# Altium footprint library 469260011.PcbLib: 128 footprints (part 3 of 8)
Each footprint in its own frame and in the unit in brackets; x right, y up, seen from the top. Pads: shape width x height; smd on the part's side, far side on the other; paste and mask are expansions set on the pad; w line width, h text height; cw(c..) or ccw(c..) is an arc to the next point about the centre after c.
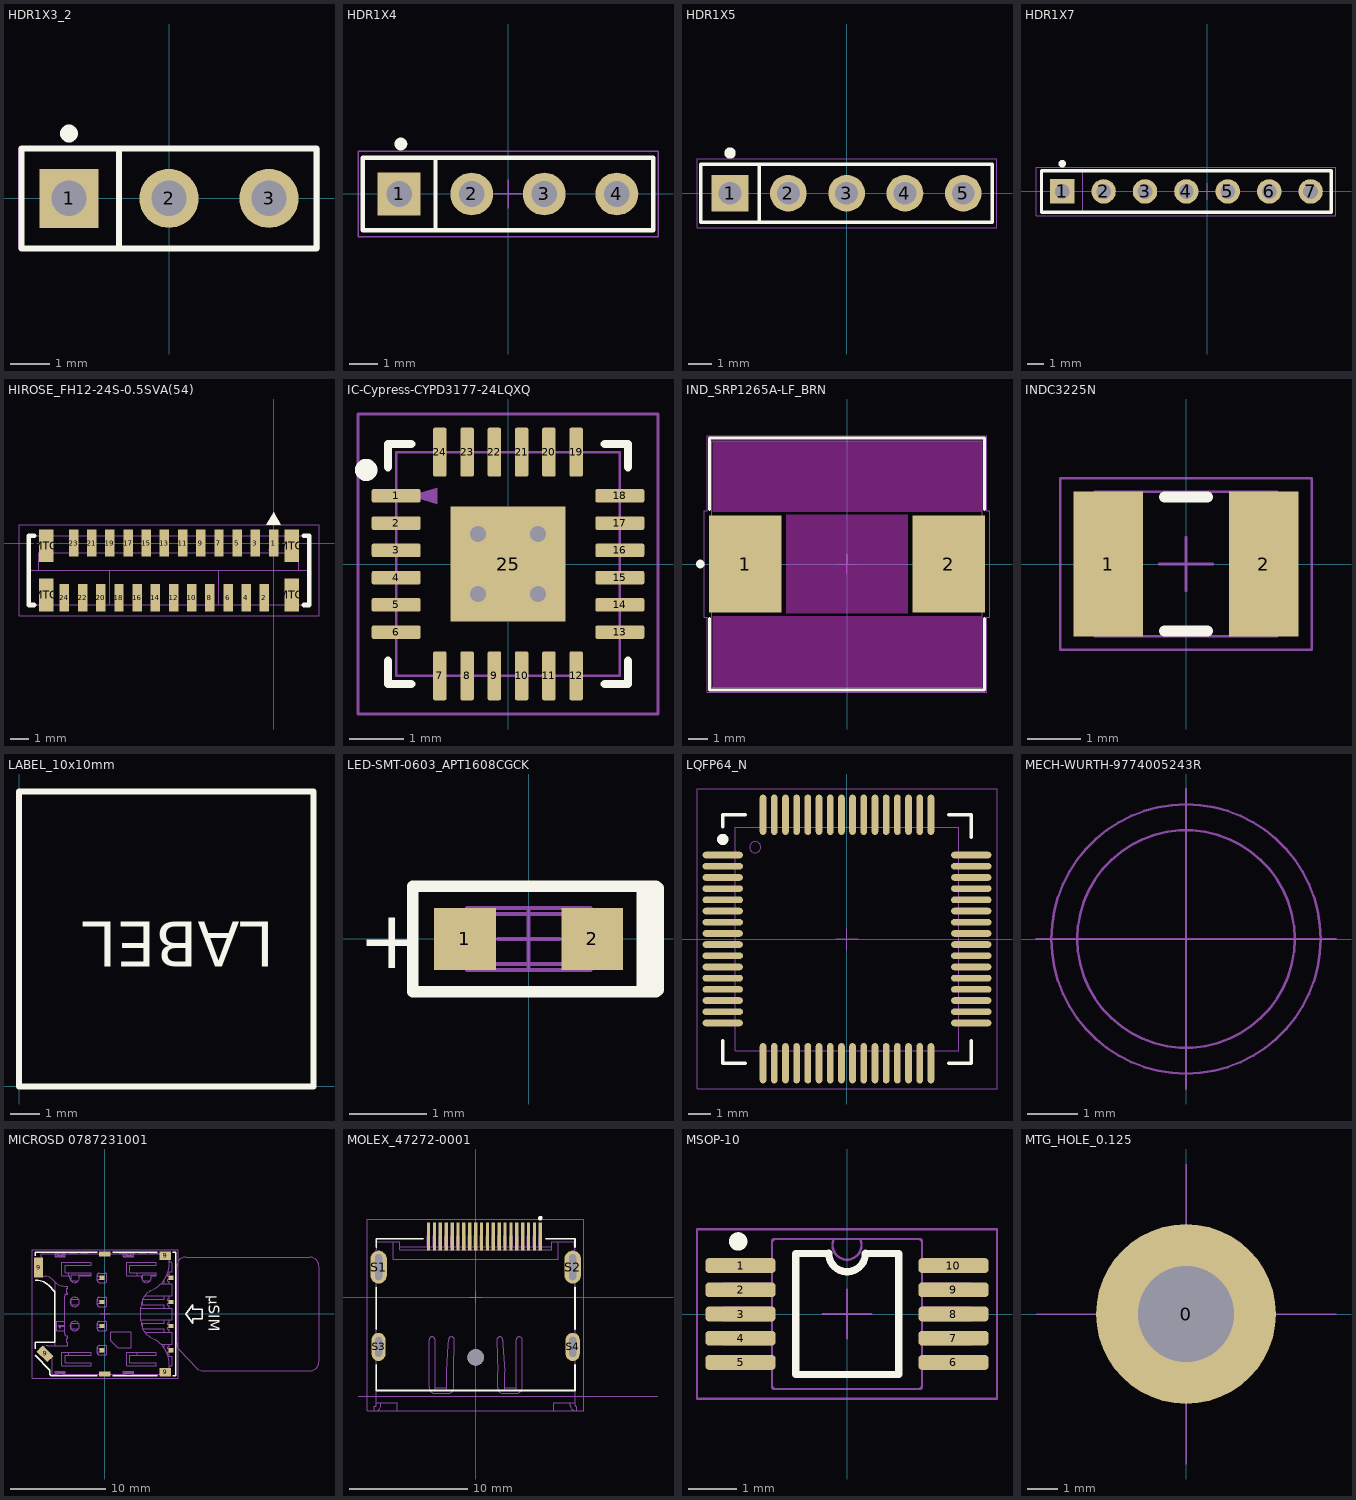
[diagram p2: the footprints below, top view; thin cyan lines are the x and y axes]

## HDR1X3_2 [mm]
pads (3):
  rect 1.5x1.5 hole 0.9: 1(-2.54,0)
  round 1.5 hole 0.9: 2(0,0) 3(2.54,0)
Top Overlay:
  circle w0.254: c-2.54,1.65 r0.1
  lines w0.15: -1.27,-1.27 -1.27,1.27 ; -3.75,-1.27 3.75,-1.27 3.75,1.27 -3.75,1.27 -3.75,-1.27
Top Assembly:
  lines w0.05: -1.27,-1.27 -1.27,1.27 ; -3.81,-1.27 3.81,-1.27 3.81,1.27 -3.81,1.27 -3.81,-1.27 ; -3,-0.45 -3,0.45 -2.1,0.45 -2.1,-0.45 -3,-0.45
  text ".Designator" at -2.252,-0.226 h1
Top Courtyard:
  lines w0.05: -0.5,0 0.5,0 ; 0,-0.5 0,0.5 ; -3.81,-1.27 3.81,-1.27 3.81,1.27 -3.81,1.27 -3.81,-1.27

## HDR1X4 [mm] "Connector; Header; 4 Position"
height 61.5
pads (4):
  rect 1.5x1.5 hole 0.9: 1(-3.81,0)
  round 1.5 hole 0.9: 2(-1.27,0) 3(1.27,0) 4(3.81,0)
Top Overlay:
  circle w0.25: c-3.75,1.75 r0.1
  lines w0.15: -2.54,-1.27 -2.54,1.27 ; -5.08,-1.27 -5.08,1.27 5.08,1.27 5.08,-1.27 -5.08,-1.27
Top Assembly:
  lines w0.05: -2.54,-1.27 -2.54,1.27 ; -5.08,-1.27 -5.08,1.27 5.08,1.27 5.08,-1.27 -5.08,-1.27 ; -4.27,-0.45 -3.37,-0.45 -3.37,0.45 -4.27,0.45 -4.27,-0.45
  text ".Designator" at -2.433,-0.226 h1
Top Courtyard:
  lines w0.05: -0.5,0 0.5,0 ; 0,-0.5 0,0.5 ; -5.25,-1.5 5.25,-1.5 5.25,1.5 -5.25,1.5 -5.25,-1.5

## HDR1X5 [mil] "Header; 5 Pos"
pads (5):
  rect 63x63 hole 39.37: 1(-200,0)
  round 63 hole 39.37: 2(-100,0) 3(0,0) 4(100,0) 5(200,0)
Top Overlay:
  circle w10: c-200,68.9 r4.72
  lines w5.91: -150,-50 -150,50 ; -250,-50 250,-50 250,50 -250,50 -250,-50
Top Assembly:
  lines w1.97: -150,-50 -150,50 ; -250,-50 250,-50 250,50 -250,50 -250,-50
  text ".Designator" at -88.67,-8.9 h39.37
Top Courtyard:
  lines w1.97: -19.69,0 19.68,0 ; 0,-19.69 0,19.68 ; -256.69,-59.06 257.87,-59.06 257.87,59.06 -256.69,59.06 -256.69,-59.06

## HDR1X7 [mm] "Connector; Header; 7 Position"
height 10
pads (7):
  rect 1.5x1.5 hole 0.9: 1(-8.89,0)
  round 1.5 hole 0.9: 2(-6.35,0) 3(-3.81,0) 4(-1.27,0) 5(1.27,0) 6(3.81,0) 7(6.35,0)
Top Overlay:
  circle w0.25: c-8.89,1.7 r0.1
  lines w0.2: 7.599,-1.27 -10.16,-1.27 -10.16,1.27 7.62,1.27 7.62,-1.27
Top Assembly:
  lines w0.05: -7.62,-1.27 -7.62,1.27 ; -10.16,-1.27 7.62,-1.27 7.62,1.27 -10.16,1.27 -10.16,-1.27 ; -9.35,-0.45 -8.45,-0.45 -8.45,0.45 -9.35,0.45 -9.35,-0.45
  text ".Designator" at -2.433,-0.226 h1
Top Courtyard:
  lines w0.05: -0.5,0 0.5,0 ; 0,-0.5 0,0.5 ; -10.5,-1.5 7.91,-1.5 7.91,1.5 -10.5,1.5 -10.5,-1.5

## HIROSE_FH12-24S-0.5SVA(54) [mm]
height 3.6
pads (28):
  rect 0.52x1.5 smd: 1(0,0) 2(-0.5,-3) 3(-1,0) 4(-1.5,-3) 5(-2,0) 6(-2.5,-3) 7(-3,0) 8(-3.5,-3) 9(-4,0) 10(-4.5,-3) 11(-5,0) 12(-5.5,-3) 13(-6,0) 14(-6.5,-3) 15(-7,0) 16(-7.5,-3) 17(-8,0) 18(-8.5,-3) 19(-9,0) 20(-9.5,-3) 21(-10,0) 22(-10.5,-3) 23(-11,0) 24(-11.5,-3)
  rect 0.8x1.8 smd: MTG(-12.5,-2.85) MTG(-12.5,-0.15) MTG(1,-2.85) MTG(1,-0.15)
Top Overlay:
  region: -0.4,1 0.4,1 0,1.7
  lines w0.254: -13.151,-3.406 -13.456,-3.406 -13.456,0.404 -13.151,0.404 ; 1.651,-3.404 1.956,-3.404 1.956,0.406 1.651,0.406
Top Assembly:
  region: -0.3,-0.4 0.3,-0.4 0,0.2
  lines w0.05: -13.44,-1.494 -12.9,-1.494 ; -9,-3.394 -9,-1.494 ; -3,-3.394 -3,-1.494 ; 1.96,-1.494 1.4,-1.494 ; -12.9,-1.494 -9,-1.494 ; -12.9,-1.494 -12.9,-0.529 1.4,-0.529 1.4,-1.494 ; -9,-1.494 -3,-1.494 ; -3,-1.494 1.4,-1.494 ; -13.44,-3.394 1.96,-3.394 1.96,0.406 -13.44,0.406 -13.44,-3.394
  text ".Designator" at -8.252,-2.426 h1
Top Courtyard:
  lines w0.05: -14,-4 2.5,-4 2.5,1 -14,1 -14,-4
3D body "FH12-24S-0.5SV.stp": height 5.45, standoff -0.05, extent -13.44,-3.394 1.96,0.406

## IC-Cypress-CYPD3177-24LQXQ [mm]
pads (25):
  rrect30% 0.9x0.25 smd mask+0.05: 1(-2.05,1.25) 2(-2.05,0.75) 3(-2.05,0.25) 4(-2.05,-0.25) 5(-2.05,-0.75) 6(-2.05,-1.25) 13(2.05,-1.25) 14(2.05,-0.75) 15(2.05,-0.25) 16(2.05,0.25) 17(2.05,0.75) 18(2.05,1.25)
  rrect30% 0.25x0.9 smd mask+0.05: 7(-1.25,-2.05) 8(-0.75,-2.05) 9(-0.25,-2.05) 10(0.25,-2.05) 11(0.75,-2.05) 12(1.25,-2.05) 19(1.25,2.05) 20(0.75,2.05) 21(0.25,2.05) 22(-0.25,2.05) 23(-0.75,2.05) 24(-1.25,2.05)
  rect 2.1x2.1 smd paste-5 mask+0.05: 25(0,0)
via -0.55,0.55 diameter 0.6 hole 0.3
via 0.55,0.55 diameter 0.6 hole 0.3
via 0.55,-0.55 diameter 0.6 hole 0.3
via -0.55,-0.55 diameter 0.6 hole 0.3
Top Overlay:
  circle w0.25: c-2.6,1.725 r0.079
  lines w0.15: -2.2,-1.775 -2.2,-2.2 -1.775,-2.2 ; -2.2,1.775 -2.2,2.2 -1.775,2.2 ; 1.775,-2.2 2.2,-2.2 2.2,-1.775 ; 1.775,2.2 2.2,2.2 2.2,1.775
Top Paste:
  region: 0.55,0.25 0.491,0.256 0.383,0.301 0.301,0.383 0.256,0.491 0.25,0.55 0.25,1.05 -0.25,1.05 -0.25,0.55 -0.256,0.491 -0.3,0.383 -0.383,0.3 -0.491,0.256 -0.55,0.25 -1.05,0.25 -1.05,-0.25 -0.55,-0.25 -0.491,-0.256 -0.383,-0.3 -0.301,-0.383 -0.256,-0.491 -0.25,-0.55 -0.25,-1.05 0.25,-1.05 0.25,-0.55 0.256,-0.491 0.301,-0.383 0.383,-0.301 0.491,-0.256 0.55,-0.25 1.05,-0.25 1.05,0.25
Top 3D Body:
  lines w0.001: -2.05,-2.05 2.05,-2.05 2.05,2.05 -2.05,2.05 -2.05,-2.05
Top Assembly:
  region: -1.298,1.4 -1.798,1.25 -1.298,1.1
  lines w0.05: -2.05,-2.05 -2.05,2.05 2.05,2.05 2.05,-2.05 -2.05,-2.05
  text ".Designator" at -1.689,-0.17 h0.75
Top Courtyard:
  lines w0.05: -0.5,0 0.5,0 ; 0,-0.5 0,0.5 ; -2.75,-2.75 2.75,-2.75 2.75,2.75 -2.75,2.75 -2.75,-2.75
3D body "QFN127P600-8N_temp.step": height 0.6, standoff 0, extent -2.051,-2.051 2.051,2.051

## IND_SRP1265A-LF_BRN [mil] "13.50mm x 12.50mm"
height 251.97
pads (2):
  rect 147.59x197 smd paste+0 mask+0: 1(-207.61,0) 2(207.61,0)
Top Layer keep-out:
  region: -273.5,106.3 -273.5,250 273.5,250 273.5,106.3
  region: -124.02,-100.5 -124.02,100.5 124.02,100.5 124.02,-100.5
  region: -273.5,-106.3 -273.5,-250 273.5,-250 273.5,-106.3
Top Overlay:
  circle w9.84: c-299.21,0 r3.94
  lines w5.91: -280.5,-111.6 -280.5,-257 280.5,-257 280.5,-111.6 ; -280.5,111.6 -280.5,257 280.5,257 280.5,111.6
Top Assembly:
  circle w1.97: c-234.25,0 r9.84
  lines w1.97: -275.5,-252 -275.5,252 275.5,252 275.5,-252 -275.5,-252
  text ".Designator" at -88.67,-8.9 h39.37
Top Courtyard:
  lines w1.97: -19.68,0.01 19.69,-0.01 ; -0.01,-19.69 0.01,19.68 ; -291.41,-108.5 -285.5,-108.5 -285.5,-262 285.5,-262 285.5,-108.5 291.41,-108.5 291.41,108.5 285.5,108.5 285.5,262 -285.5,262 -285.5,108.5 -291.41,108.5 -291.41,-108.5
3D body "IND_SRP1265A-LF_BRN.step": height 248.03, standoff 0, extent -259.84,-246.06 248.03,246.06

## INDC3225N [mm] "Chip Inductor, Body 3.2x2.5mm, IPC Medium Density / 3D - INDC3225x135N"
height 1.5
pads (2):
  rect 1.3x2.7 smd: 1(-1.45,0) 2(1.45,0)
Top Overlay:
  lines w0.2: -0.4,-1.25 0.4,-1.25 ; -0.4,1.25 0.4,1.25
Top Assembly:
  lines w0.05: -1.7,-1.35 1.7,-1.35 1.7,1.35 -1.7,1.35 -1.7,-1.35
  text ".Designator" at -2.252,-0.226 h1
Top Courtyard:
  lines w0.05: -0.5,0 0.5,0 ; 0,-0.5 0,0.5 ; -2.35,-1.6 -2.35,1.6 2.35,1.6 2.35,-1.6 -2.35,-1.6
3D body "User Library-Chip Inductor.step": height 1.35, standoff 0, extent -1.6,-1.25 1.6,1.25

## LABEL_10x10mm [mm]
height 14
Top Overlay:
  lines w0.203: 0,0 10,0 10,10 0,10 0,0
  text "LABEL" at 8.659,5.588 h1.52

## LED-SMT-0603_APT1608CGCK [mm] "LED SMT Green, 2-Leads, Body 1,00x0,80mm, IPC Medium Density"
height 0.75
pads (2):
  rect 0.8x0.8 smd: 1(-0.825,0) 2(0.825,0)
Top Overlay:
  lines w0.15: 1.473,-0.66 1.473,0.66 ; 1.55,-0.65 1.55,0.671 ; -1.499,-0.686 -1.499,0.686 1.651,0.686 1.676,0.66 1.676,-0.66 1.651,-0.686 -1.499,-0.686
  text "+" at -2.21,-0.381 h0.76
Top Assembly:
  circle w0.05: c0.7,0.3 r0.05
  lines w0.05: -0.8,-0.4 -0.8,-0.2 ccw(c-0.8,0) -0.8,0.2 -0.8,0.4 -0.4,0.4 0.4,0.4 0.8,0.4 0.8,0.2 ccw(c0.8,0) 0.8,-0.2 0.8,-0.4 0.4,-0.4 -0.4,-0.4 -0.8,-0.4 ; -0.472,-0.322 -0.472,0.322 0.472,0.322 0.472,-0.322 -0.472,-0.322
  text ".Designator" at -2.252,-0.226 h1
Top Courtyard:
  lines w0.05: -0.4,0 0.4,0 ; 0,-0.4 0,0.4 ; -1.499,-0.7 1.676,-0.7 1.676,0.7 -1.499,0.7 -1.499,-0.7
3D body "User Library-LED_0603_G.STEP": height 0.6, standoff 0, extent -0.8,-0.4 0.8,0.4

## LQFP64_N [mm] "Thin QFP, 64-Leads, Body 10x10mm, Pitch 0.5mm, IPC Medium Density"
height 1.6
pads (64):
  oval 1.8x0.3 smd: 1(-5.55,3.75) 2(-5.55,3.25) 3(-5.55,2.75) 4(-5.55,2.25) 5(-5.55,1.75) 6(-5.55,1.25) 7(-5.55,0.75) 8(-5.55,0.25) 9(-5.55,-0.25) 10(-5.55,-0.75) 11(-5.55,-1.25) 12(-5.55,-1.75) 13(-5.55,-2.25) 14(-5.55,-2.75) 15(-5.55,-3.25) 16(-5.55,-3.75) 33(5.55,-3.75) 34(5.55,-3.25) 35(5.55,-2.75) 36(5.55,-2.25) 37(5.55,-1.75) 38(5.55,-1.25) 39(5.55,-0.75) 40(5.55,-0.25) 41(5.55,0.25) 42(5.55,0.75) 43(5.55,1.25) 44(5.55,1.75) 45(5.55,2.25) 46(5.55,2.75) 47(5.55,3.25) 48(5.55,3.75)
  oval 0.3x1.8 smd: 17(-3.75,-5.55) 18(-3.25,-5.55) 19(-2.75,-5.55) 20(-2.25,-5.55) 21(-1.75,-5.55) 22(-1.25,-5.55) 23(-0.75,-5.55) 24(-0.25,-5.55) 25(0.25,-5.55) 26(0.75,-5.55) 27(1.25,-5.55) 28(1.75,-5.55) 29(2.25,-5.55) 30(2.75,-5.55) 31(3.25,-5.55) 32(3.75,-5.55) 49(3.75,5.55) 50(3.25,5.55) 51(2.75,5.55) 52(2.25,5.55) 53(1.75,5.55) 54(1.25,5.55) 55(0.75,5.55) 56(0.25,5.55) 57(-0.25,5.55) 58(-0.75,5.55) 59(-1.25,5.55) 60(-1.75,5.55) 61(-2.25,5.55) 62(-2.75,5.55) 63(-3.25,5.55) 64(-3.75,5.55)
Top Overlay:
  circle w0.25: c-5.55,4.45 r0.125
  lines w0.15: -5.55,-4.55 -5.55,-5.55 -4.55,-5.55 ; -5.55,5 -5.55,5.55 -4.55,5.55 ; 4.55,-5.55 5.55,-5.55 5.55,-4.55 ; 4.55,5.55 5.55,5.55 5.55,4.55 ; -4.65,-5.55 -4.65,-5.55
Top Assembly:
  circle w0.05: c-4.1,4.1 r0.25
  lines w0.05: -5,-5 5,-5 5,5 -5,5 -5,-5
  text ".Designator" at -2.252,-0.226 h1
Top Courtyard:
  lines w0.05: -0.5,0 0.5,0 ; 0,-0.5 0,0.5 ; -6.7,-6.7 6.7,-6.7 6.7,6.7 -6.7,6.7 -6.7,-6.7
3D body "User Library-LQFP-64-1.step": height 1.5, standoff 0, extent -6,-6 6,6

## MECH-WURTH-9774005243R [mm]
height 0.5
Mechanical 1:
  lines w0.05: -3,0 3,0 ; 0,-3 0,3
Top Assembly:
  circle w0.05: c0,0 r2.175
  text ".Designator" at -1.689,-0.17 h0.75
Top Courtyard:
  circle w0.05: c0,0 r2.693
  lines w0.05: -0.5,0 0.5,0 ; 0,-0.5 0,0.5
3D body "STP_9774005243 (rev1).stp": height 0.5, standoff -0.9, extent -2.175,-2.163 2.175,2.163

## MICROSD 0787231001 [mm]
height 1.35
pads (14):
  rect 0.94x2.1 smd: 9(-6.98,4.88)
  rect 0.94x1.6 smd rot 45: 9(-6.3,-4.19)
  rect 1.2x0.52 smd: 9(-0.02,-6.31) 9(-0.02,6.31)
  rect 1.2x0.89 smd: 9(6.37,-6.125) 9(6.37,6.125)
  rect 0.52x0.45 smd: C1(6.98,3.81) C2(6.98,1.27) C3(6.98,-1.27) C4(6.98,-3.81) C5(-0.28,3.81) C6(-0.28,1.27) C7(-0.28,-1.27) C8(-0.28,-3.81)
Top Overlay:
  lines w0.15: 8.5,0 9.25,1 9.25,0.5 10.25,0.5 10.25,-0.5 9.25,-0.5 9.25,-1 8.5,0
  lines w0.152: -7.354,-3.683 -7.354,-2.997 -5.271,-2.997 -5.271,2.362 -5.931,3.023 ccw(c-7.219,1.735) -7.219,3.556 -7.354,3.556 ; -7.354,6.147 -7.354,6.528 -0.826,6.528 ; -7.35,-4.35 -5.8,-5.9 -5.8,-6.35 -5.622,-6.528 -0.826,-6.528 ; 0.825,-6.528 5.524,-6.528 ; 0.825,6.528 5.524,6.528 ; 7.175,-6.528 7.454,-6.528 7.454,6.528 7.175,6.528
  text "μSIM" at 10.526,1.97 h2
Top Assembly:
  drawing of 385 lines, arcs and shapes, not listed
  text "μSIM" at 10.526,1.97 h2
  text ".Designator" at -2.252,-0.226 h1
Top Courtyard:
  lines w0.05: -0.5,0 0.5,0 ; 0,-0.5 0,0.5 ; -7.65,-6.75 -7.65,6.75 7.75,6.75 7.75,-6.75 -7.65,-6.75
3D body "787231001.stp": height 1.34, standoff 0, extent -7.329,-6.406 7.091,6.394
3D body "User Library-Micro Sim Card.step": height 1.17, standoff 0.5, extent 7.55,-6 22.55,6

## MOLEX_47272-0001 [mm] "CONN RCPT DISPLAYPORT 20P SMD RA"
pads (25):
  rect 0.28x2.4 smd: 1(5.5,5.14) 2(5,5.14) 3(4.5,5.14) 4(4,5.14) 5(3.5,5.14) 6(3,5.14) 7(2.5,5.14) 8(2,5.14) 9(1.5,5.14) 10(1,5.14) 11(0.5,5.14) 12(0,5.14) 13(-0.5,5.14) 14(-1,5.14) 15(-1.5,5.14) 16(-2,5.14) 17(-2.5,5.14) 18(-3,5.14) 19(-3.5,5.14) 20(-4,5.14)
  oval 1.4x2.8 hole 0.6 slot 2.2 at 90 deg: S1(-8.25,2.54) S2(8.25,2.54)
  oval 1.2x2.4 hole 0.6 slot 1.7 at 90 deg: S3(-8.25,-4.24) S4(8.25,-4.24)
  round 1.4 hole 1.4 unplated: ""(0,-5.14)
Top Overlay:
  circle w0.2: c5.5,6.7 r0.1
  lines w0.15: -8.45,-5.76 -8.45,-7.94 8.45,-7.94 8.45,-5.76 ; -8.45,-2.73 -8.45,0.82 ; -8.45,4.25 -8.45,4.95 -4.45,4.95 ; 5.95,4.95 8.45,4.95 8.45,4.25 ; 8.45,-2.73 8.45,0.82
Mechanical 1:
  lines w0.05: -10,-8.42 15.5,-8.42
  text "PCB EDGE" at 3.55,-8.2 h0.81
Top Assembly:
  drawing of 408 lines, arcs and shapes, not listed
  text ".Designator" at -2.252,-0.226 h1
Top Courtyard:
  lines w0.05: -0.5,0 0.5,0 ; 0,-0.5 0,0.5 ; -9.2,-9.69 -9.2,6.59 9.2,6.59 9.2,-9.69 -9.2,-9.69
3D body "472720001.stp": height 6.7, standoff -2.05, extent -8.895,-9.12 8.89,5.77

## MSOP-10 [mm] "10-VSSOP, 10-TFSOP, 10-MSOP (0.118\", 3.00mm Width), 0.5mm pitch, DGS0010A (TI)"
height 1.1
pads (10):
  rrect50% 1.45x0.305 smd: 1(-2.2,1.001) 2(-2.2,0.5) 3(-2.2,0) 4(-2.2,-0.5) 5(-2.2,-1.001) 6(2.2,-1.001) 7(2.2,-0.5) 8(2.2,0) 9(2.2,0.5) 10(2.2,1.001)
Top Overlay:
  circle w0.2: c-2.25,1.5 r0.09
  lines w0.15: -0.375,1.251 ccw(c0.002,1.251) 0.379,1.251 ; -0.375,1.256 -1.057,1.251 -1.057,-1.251 1.071,-1.251 1.071,1.251 ; 0.383,1.255 1.071,1.25
Top Assembly:
  drawing of 587 lines, arcs and shapes, not listed
  text ".Designator" at -1.702,-0.207 h1
Top Courtyard:
  lines w0.05: -0.5,0 0.5,0 ; 0,-0.5 0,0.5 ; -3.1,-1.75 -3.1,1.75 3.1,1.75 3.1,-1.75 -3.05,-1.75 -3.1,-1.75
3D body "User Library-MSOP10-2.step": height 1.03, standoff 0, extent -2.557,-1.55 2.557,1.55

## MTG_HOLE_0.125 [mm] "Mounting hole 0,125\" (3.2 mm)"
pads (1):
  round 6 hole 3.2 paste+0: 0(0,0)
Mechanical 1:
  lines w0.05: -5,0 5,0 ; 0,-5 0,5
